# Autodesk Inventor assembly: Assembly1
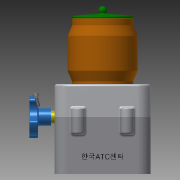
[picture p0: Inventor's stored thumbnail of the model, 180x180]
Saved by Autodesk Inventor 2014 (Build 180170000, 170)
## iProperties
Created: 2018-01
Part Number: Assembly1
Document SubType Name: Assembly
Designer: Administrator
Author: Administrator
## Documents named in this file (9)
- C:\Users\Administrator\Desktop\480108V1018\480108V1018\Assembly1.iam
- C:\Users\Administrator\Desktop\480108V1018\480108V1018\본체.ipt
- C:\Users\Administrator\Desktop\480108V1018\480108V1018\본체커버.ipt
- C:\Users\Administrator\Desktop\480108V1018\480108V1018\볼트 M3x12.ipt
- C:\Users\Administrator\Desktop\480108V1018\480108V1018\볼트 M4x12.ipt
- C:\Users\Administrator\Desktop\480108V1018\480108V1018\용기.ipt
- C:\Users\Administrator\Desktop\480108V1018\480108V1018\용기캡.ipt
- C:\Users\Administrator\Desktop\480108V1018\480108V1018\핸들.ipt
- C:\Users\Administrator\Desktop\480108V1018\480108V1018\핸들축.ipt
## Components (2 placed, 2 different names)
1. 핸들:1 — Mate:1, Mate:2, Mate:3, Mate:4, Mate:5
2. 핸들축:1 — Mate:1, Mate:2, Mate:3, Mate:6, Mate:7
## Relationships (7: Mate 7)
- Mate:1: 핸들:1 ↔ 핸들축:1
- Mate:2: 핸들:1 ↔ 핸들축:1
- Mate:3: 핸들:1 ↔ 핸들축:1
- Mate:4: 핸들:1
- Mate:5: 핸들:1
- Mate:6: 핸들축:1
- Mate:7: 핸들축:1
